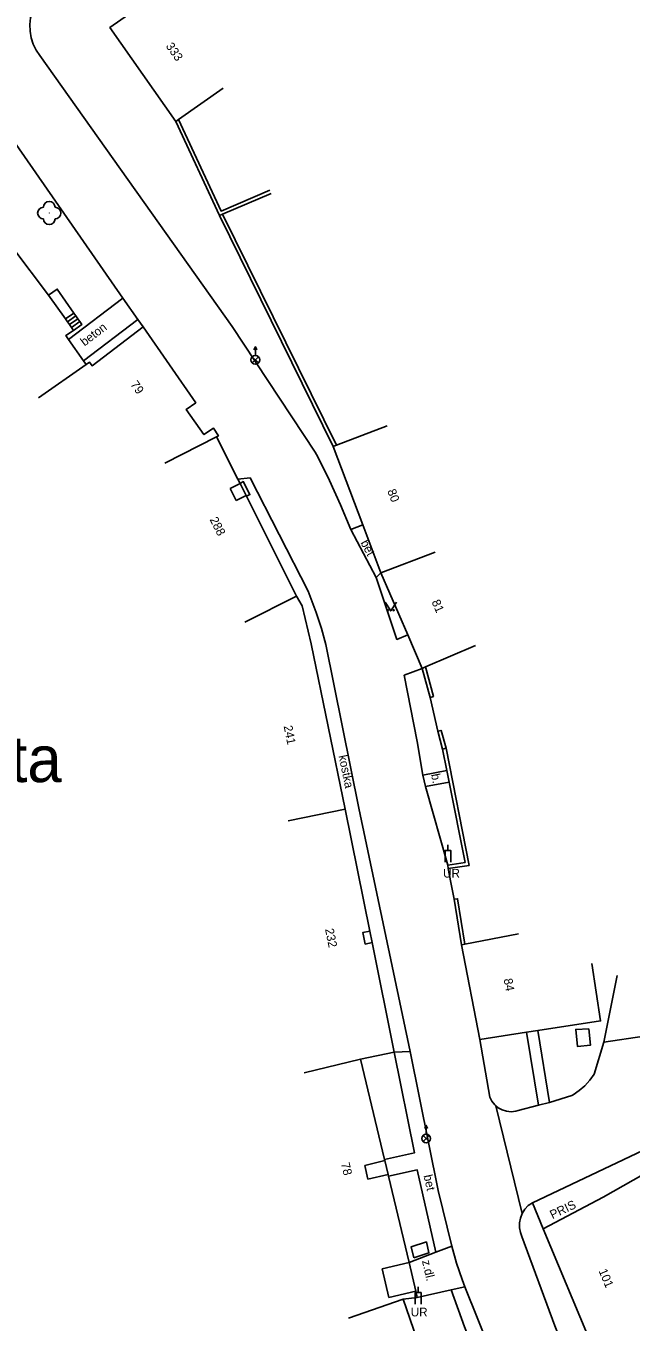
# Model space of a CAD drawing. Extents: x -544674 to -541478, y -1199076 to -1195527.
# Drawn here: x -542737.5 to -542685.3, y -1198126.6 to -1198014.8 of the extents above; entities that cross this region are included whole.
import ezdxf

# ---------------------------------------------------------------- set-up
doc = ezdxf.new("R2010")
doc.units = 0
for name, color, linetype in [('BUDOVY_MĚŘ', 7, 'Continuous'), ('NÁZVY_SÍDEL_JEDNOTKY', 7, 'Continuous'), ('POMOC_POPIS', 7, 'Continuous'), ('ROZHRANÍ_PLOCH', 7, 'Continuous'), ('ZELEŇ', 7, 'Continuous'), ('ZN_BP', 7, 'Continuous'), ('ZN_DOPLŇKOVÉ', 7, 'Continuous'), ('ZN_KULTUR', 7, 'Continuous'), ('Č_POPIS_ORIENT', 7, 'Continuous')]:
    doc.layers.add(name, color=color, linetype=linetype)

msp = doc.modelspace()

# ---------------------------------------------------------------- linework, layer by layer
at = {"layer": 'BUDOVY_MĚŘ'}
for points in [[(-542724.59, -1198023.03), (-542730.27, -1198014.94), (-542722.72, -1198009.64)], [(-542720.5, -1198020.16), (-542724.34, -1198022.86)], [(-542724.34, -1198022.86), (-542724.59, -1198023.03)], [(-542738.65, -1198033.93), (-542735.55, -1198038.01)], [(-542735.55, -1198038.01), (-542734.11, -1198040.06)], [(-542734.11, -1198040.06), (-542733.93, -1198040.31)], [(-542733.93, -1198040.31), (-542733.76, -1198040.55)], [(-542733.76, -1198040.55), (-542733.59, -1198040.8)], [(-542733.59, -1198040.8), (-542733.42, -1198041.05)], [(-542727.41, -1198040.75), (-542731.81, -1198044.09), (-542732.02, -1198043.79), (-542732.32, -1198044)], [(-542721.08, -1198050.24), (-542720.91, -1198050.13), (-542721.32, -1198049.49), (-542722.16, -1198050.03), (-542723.68, -1198047.86), (-542722.86, -1198047.29), (-542727.41, -1198040.75)], [(-542733.42, -1198041.05), (-542734.07, -1198041.5), (-542733.84, -1198041.82)], [(-542733.84, -1198041.82), (-542732.55, -1198043.68)], [(-542736.42, -1198046.87), (-542732.32, -1198044)], [(-542732.55, -1198043.68), (-542732.32, -1198044)], [(-542710.73, -1198050.95), (-542706.34, -1198049.29)], [(-542725.53, -1198052.5), (-542721.08, -1198050.24)], [(-542721.08, -1198050.24), (-542719.22, -1198053.89)], [(-542711.01, -1198051.06), (-542710.73, -1198050.95)], [(-542708.44, -1198057.82), (-542711.01, -1198051.06)], [(-542719.22, -1198053.89), (-542719.04, -1198054.25)], [(-542719.04, -1198054.25), (-542718.52, -1198055.29)], [(-542718.52, -1198055.29), (-542718.49, -1198055.35)], [(-542718.49, -1198055.35), (-542714.16, -1198063.96)], [(-542706.88, -1198061.94), (-542708.44, -1198057.82)], [(-542702.2, -1198060.17), (-542706.88, -1198061.94)], [(-542704.57, -1198067.3), (-542706.88, -1198061.94)], [(-542718.63, -1198066.21), (-542714.16, -1198063.96)], [(-542714.16, -1198063.96), (-542713.69, -1198064.8), (-542712.91, -1198068.08), (-542709.98, -1198082.32)], [(-542703.32, -1198070.19), (-542704.57, -1198067.3)], [(-542698.73, -1198068.21), (-542703.04, -1198070.07)], [(-542703.04, -1198070.07), (-542703.32, -1198070.19)], [(-542714.88, -1198083.33), (-542709.98, -1198082.32)], [(-542709.98, -1198082.32), (-542707.85, -1198092.84)], [(-542707.85, -1198092.84), (-542708.44, -1198092.96), (-542708.24, -1198093.96), (-542707.65, -1198093.84)], [(-542707.85, -1198092.84), (-542707.65, -1198093.84)], [(-542699.64, -1198093.97), (-542695.02, -1198093.07)], [(-542707.65, -1198093.84), (-542705.74, -1198103.3)], [(-542699.93, -1198094.03), (-542699.64, -1198093.97)], [(-542698.34, -1198102.18), (-542699.93, -1198094.03)], [(-542688.7, -1198095.65), (-542687.94, -1198100.59), (-542693.36, -1198101.42)], [(-542694.33, -1198101.57), (-542698.34, -1198102.18)], [(-542693.36, -1198101.42), (-542694.33, -1198101.57)], [(-542705.74, -1198103.3), (-542708.65, -1198103.9)], [(-542713.51, -1198105.07), (-542708.65, -1198103.9)], [(-542708.65, -1198103.9), (-542706.57, -1198112.55)], [(-542681.86, -1198112.47), (-542687.7, -1198115.79), (-542692.9, -1198118.51)], [(-542706.57, -1198112.55), (-542706.55, -1198112.63)], [(-542706.55, -1198112.63), (-542706.27, -1198113.83)], [(-542706.27, -1198113.83), (-542706.23, -1198113.99)], [(-542706.23, -1198113.99), (-542704.46, -1198121.41)], [(-542692.9, -1198118.51), (-542688.39, -1198129.23), (-542688.3, -1198129.19)], [(-542704.46, -1198121.41), (-542703.88, -1198123.9)], [(-542709.69, -1198126.22), (-542704.96, -1198124.59)], [(-542703.75, -1198124.44), (-542704.96, -1198124.59)], [(-542704.96, -1198124.59), (-542702, -1198133.19)], [(-542703.88, -1198123.9), (-542703.75, -1198124.44)]]:
    msp.add_lwpolyline(points, dxfattribs=at)
at = {"layer": 'ROZHRANÍ_PLOCH'}
for points in [[(-542709.49, -1198058.22), (-542710.37, -1198056.1), (-542711.32, -1198054), (-542712.34, -1198051.94), (-542712.55, -1198051.54), (-542719.71, -1198040.7), (-542736.31, -1198017.35), (-542736.63, -1198016.87), (-542736.88, -1198016.36), (-542737.05, -1198015.81), (-542737.15, -1198015.25), (-542737.17, -1198014.67), (-542737.11, -1198014.1), (-542736.97, -1198013.55), (-542736.75, -1198013.01), (-542736.46, -1198012.52), (-542736.11, -1198012.07), (-542735.69, -1198011.67), (-542735.51, -1198011.52), (-542732.78, -1198009.55), (-542726.04, -1198004.59)], [(-542729.15, -1198038.26), (-542740.08, -1198022.58)], [(-542733.37, -1198039.55), (-542734.81, -1198037.49), (-542735.55, -1198038.01)], [(-542733.84, -1198041.82), (-542729.15, -1198038.26)], [(-542727.85, -1198040.12), (-542729.15, -1198038.26)], [(-542734.11, -1198040.06), (-542733.37, -1198039.55)], [(-542733.93, -1198040.31), (-542733.2, -1198039.79)], [(-542733.2, -1198039.79), (-542733.37, -1198039.55)], [(-542733.02, -1198040.04), (-542733.2, -1198039.79)], [(-542733.76, -1198040.55), (-542733.02, -1198040.04)], [(-542733.59, -1198040.8), (-542732.85, -1198040.28)], [(-542733.42, -1198041.05), (-542732.68, -1198040.53), (-542732.85, -1198040.28)], [(-542732.85, -1198040.28), (-542733.02, -1198040.04)], [(-542732.55, -1198043.68), (-542727.85, -1198040.12)], [(-542727.41, -1198040.75), (-542727.85, -1198040.12)], [(-542719.04, -1198054.25), (-542719.89, -1198054.68)], [(-542704.36, -1198103.22), (-542708.78, -1198082.25), (-542711.65, -1198068.14), (-542712.02, -1198066.75), (-542712.46, -1198065.38), (-542712.63, -1198064.91), (-542713.17, -1198063.53), (-542718.17, -1198053.77), (-542719.22, -1198053.89)], [(-542719.04, -1198054.25), (-542718.76, -1198054.09), (-542718.19, -1198055.2), (-542718.49, -1198055.35)], [(-542719.37, -1198055.72), (-542719.89, -1198054.68)], [(-542718.52, -1198055.29), (-542719.37, -1198055.72)], [(-542708.44, -1198057.82), (-542709.49, -1198058.22)], [(-542709.49, -1198058.22), (-542707.3, -1198062.36)], [(-542707.3, -1198062.36), (-542706.88, -1198061.94)], [(-542704.57, -1198067.3), (-542705.5, -1198067.7), (-542707.3, -1198062.36)], [(-542703.28, -1198079.4), (-542703.76, -1198076.51), (-542704.87, -1198070.78), (-542703.32, -1198070.19)], [(-542701.2, -1198078.99), (-542703.28, -1198079.4)], [(-542703.03, -1198080.39), (-542703.28, -1198079.4)], [(-542701, -1198079.99), (-542703.03, -1198080.39)], [(-542701.12, -1198087.16), (-542703.03, -1198080.39)], [(-542701.07, -1198087.46), (-542701.12, -1198087.16)], [(-542687.65, -1198102.41), (-542686.51, -1198096.67)], [(-542688.94, -1198101.26), (-542690.07, -1198101.33), (-542689.93, -1198102.79), (-542688.8, -1198102.68), (-542688.94, -1198101.26)], [(-542698.34, -1198102.18), (-542697.5, -1198107.16), (-542697.32, -1198107.51), (-542697.07, -1198107.82), (-542696.98, -1198107.91)], [(-542693.3, -1198107.87), (-542694.33, -1198101.57)], [(-542692.35, -1198107.63), (-542693.36, -1198101.42)], [(-542692.35, -1198107.63), (-542690.42, -1198107.02), (-542690.31, -1198106.96), (-542689.77, -1198106.6), (-542689.29, -1198106.18), (-542688.86, -1198105.7), (-542688.5, -1198105.17), (-542687.65, -1198102.41)], [(-542684.17, -1198101.9), (-542687.65, -1198102.41)], [(-542706.57, -1198112.55), (-542704, -1198111.98), (-542705.74, -1198103.3)], [(-542705.74, -1198103.3), (-542704.36, -1198103.22)], [(-542700.77, -1198120.02), (-542701.96, -1198115.2), (-542704.36, -1198103.22)], [(-542696.98, -1198107.91), (-542696.77, -1198108.08), (-542696.42, -1198108.27), (-542696.05, -1198108.38), (-542695.65, -1198108.42), (-542695.26, -1198108.38), (-542695.04, -1198108.32), (-542693.3, -1198107.87)], [(-542696.98, -1198107.91), (-542694.69, -1198117.2)], [(-542693.3, -1198107.87), (-542692.35, -1198107.63)], [(-542682.58, -1198110.96), (-542693.82, -1198116.27)], [(-542706.55, -1198112.63), (-542708.28, -1198113.05)], [(-542708, -1198114.24), (-542708.28, -1198113.05)], [(-542702.16, -1198120.54), (-542703.75, -1198113.44), (-542706.23, -1198113.99)], [(-542706.27, -1198113.83), (-542708, -1198114.24)], [(-542693.82, -1198116.27), (-542694.17, -1198116.52), (-542694.46, -1198116.83), (-542694.69, -1198117.2)], [(-542692.9, -1198118.51), (-542693.82, -1198116.27)], [(-542694.69, -1198117.2), (-542694.84, -1198117.59), (-542694.92, -1198118), (-542694.93, -1198118.43), (-542694.85, -1198118.85), (-542694.72, -1198119.19), (-542691.89, -1198126.89), (-542690.47, -1198130.35), (-542681.77, -1198148.59)], [(-542704.06, -1198121.01), (-542702.75, -1198120.59), (-542702.96, -1198119.65), (-542704.27, -1198120.07), (-542704.06, -1198121.01)], [(-542702.16, -1198120.54), (-542700.77, -1198120.02)], [(-542700.77, -1198120.02), (-542700.36, -1198121.47), (-542699.88, -1198122.9), (-542699.65, -1198123.51)], [(-542704.46, -1198121.41), (-542706.79, -1198121.96)], [(-542704.46, -1198121.41), (-542702.16, -1198120.54)], [(-542706.2, -1198124.44), (-542706.79, -1198121.96)], [(-542699.65, -1198123.51), (-542700.82, -1198123.78)], [(-542699.65, -1198123.51), (-542697.34, -1198129.25), (-542694.96, -1198134.96), (-542693.01, -1198139.47), (-542690.95, -1198143.73), (-542688.82, -1198147.95), (-542686.62, -1198152.13), (-542686.43, -1198152.48)], [(-542703.88, -1198123.9), (-542706.2, -1198124.44)], [(-542700.82, -1198123.78), (-542703.75, -1198124.44)], [(-542687.78, -1198153.01), (-542694.09, -1198139.93), (-542694.35, -1198139.41), (-542695.79, -1198136.34), (-542697.16, -1198133.25), (-542698.45, -1198130.12), (-542699.67, -1198126.97), (-542700.82, -1198123.78)]]:
    msp.add_lwpolyline(points, dxfattribs=at)
at = {"layer": 'ZELEŇ'}
msp.add_circle((-542735.5, -1198030.93), 0.0005, dxfattribs=at)
for centre, start, end in [((-542736, -1198030.93), 89.99999, 269.99999), ((-542735.5, -1198030.43), 0, 179.99999), ((-542735, -1198030.93), 270, 89.99999), ((-542735.5, -1198031.43), 179.99999, 359.99999)]:
    msp.add_arc(centre, 0.5, start, end, dxfattribs=at)
at = {"layer": 'ZN_BP'}
for p, q in [((-542717.72, -1198043.215), (-542717.72, -1198042.465)), ((-542717.985, -1198043.854), (-542717.456, -1198043.326)), ((-542717.456, -1198043.858), (-542717.985, -1198043.326)), ((-542702.98, -1198110.355), (-542702.98, -1198109.605)), ((-542703.245, -1198110.994), (-542702.716, -1198110.466)), ((-542702.716, -1198110.998), (-542703.245, -1198110.466))]:
    msp.add_line(p, q, dxfattribs=at)
for points in [[(-542717.845, -1198042.715), (-542717.72, -1198042.465), (-542717.595, -1198042.715)], [(-542703.105, -1198109.855), (-542702.98, -1198109.605), (-542702.855, -1198109.855)]]:
    msp.add_lwpolyline(points, dxfattribs=at)
for centre in [(-542717.72, -1198043.59), (-542702.98, -1198110.73)]:
    msp.add_circle(centre, 0.375, dxfattribs=at)
at = {"layer": 'ZN_DOPLŇKOVÉ'}
for p, q in [((-542701.1, -1198085.9), (-542701.1, -1198085.4)), ((-542703.67, -1198124.01), (-542703.67, -1198123.51))]:
    msp.add_line(p, q, dxfattribs=at)
for points in [[(-542724.59, -1198023.03), (-542720.82, -1198031.15)], [(-542716.48, -1198028.96), (-542720.67, -1198030.76), (-542724.34, -1198022.86)], [(-542720.54, -1198031.03), (-542716.36, -1198029.23)], [(-542720.82, -1198031.15), (-542720.54, -1198031.03)], [(-542711.01, -1198051.06), (-542720.82, -1198031.15)], [(-542710.73, -1198050.95), (-542720.54, -1198031.03)], [(-542703.32, -1198070.19), (-542702.64, -1198072.71)], [(-542702.64, -1198072.71), (-542702.35, -1198072.63), (-542703.04, -1198070.07)], [(-542702.64, -1198072.71), (-542701.98, -1198075.62)], [(-542701.98, -1198075.62), (-542701.69, -1198075.54), (-542701.27, -1198077.07)], [(-542701.98, -1198075.62), (-542701.56, -1198077.15)], [(-542701.27, -1198077.07), (-542701.56, -1198077.15)], [(-542701.56, -1198077.15), (-542701.2, -1198078.99)], [(-542701.07, -1198087.46), (-542699.28, -1198087.18), (-542701.27, -1198077.07)], [(-542701.2, -1198078.99), (-542701, -1198079.99)], [(-542701, -1198079.99), (-542699.63, -1198086.93), (-542701.12, -1198087.16)], [(-542701.35, -1198086.9), (-542701.35, -1198085.9), (-542700.85, -1198085.9), (-542700.85, -1198086.9)], [(-542701.07, -1198087.46), (-542700.84, -1198088.65)], [(-542700.84, -1198088.65), (-542700.57, -1198090.1)], [(-542699.64, -1198093.97), (-542700.27, -1198090.05), (-542700.57, -1198090.1)], [(-542700.57, -1198090.1), (-542699.93, -1198094.03)], [(-542703.92, -1198125.01), (-542703.92, -1198124.01), (-542703.42, -1198124.01), (-542703.42, -1198125.01)]]:
    msp.add_lwpolyline(points, dxfattribs=at)
at = {"layer": 'ZN_KULTUR'}
msp.add_lwpolyline([(-542706.53, -1198064.48), (-542706.03, -1198065.23), (-542705.53, -1198064.48)], dxfattribs=at)
for centre in [(-542706.28, -1198065.18), (-542705.78, -1198065.18)]:
    msp.add_circle(centre, 0.05, dxfattribs=at)

# ---------------------------------------------------------------- texts
at = {"layer": 'NÁZVY_SÍDEL_JEDNOTKY'}
msp.add_text('Hroznová Lhota', height=4, dxfattribs=at).set_placement((-542772.18, -1198080))
at = {"layer": 'POMOC_POPIS'}
for s, rotation, p in [('beton', 37.17001, (-542732.46, -1198042.44)), ('bet', 297.88001, (-542708.67, -1198059.35)), ('kostka', 281.63001, (-542710.54, -1198077.74)), ('b.', 281.16002, (-542702.56, -1198079.34)), ('bet', 282.61, (-542703.21, -1198113.93)), ('PRIS', 25.29001, (-542692.09, -1198117.69)), ('z.dl.', 283.19001, (-542703.35, -1198121.29))]:
    msp.add_text(s, height=0.75, rotation=rotation, dxfattribs=at).set_placement(p)
for p in [(-542701.52, -1198088.23), (-542704.31, -1198126.07)]:
    msp.add_text('UR', height=0.75, dxfattribs=at).set_placement(p)
at = {"layer": 'Č_POPIS_ORIENT'}
for s, rotation, p in [('333', 305.07, (-542725.48, -1198016.54)), ('79', 304.82999, (-542728.53, -1198045.71)), ('80', 290.79, (-542706.35, -1198054.89)), ('288', 296.68001, (-542721.68, -1198057.35)), ('81', 293.34001, (-542702.53, -1198064.45)), ('241', 281.63001, (-542715.28, -1198075.18)), ('232', 281.42999, (-542711.71, -1198092.68)), ('84', 281.03998, (-542696.3, -1198096.99)), ('78', 283.51997, (-542710.34, -1198112.89)), ('101', 292.81999, (-542688.12, -1198122.14))]:
    msp.add_text(s, height=0.75, rotation=rotation, dxfattribs=at).set_placement(p)

doc.saveas('drawing.dxf')
